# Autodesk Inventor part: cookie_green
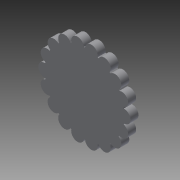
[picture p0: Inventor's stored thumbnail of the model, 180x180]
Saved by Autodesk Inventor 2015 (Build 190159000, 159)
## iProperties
Created: 2017-04
Part Number: cookie_green
Material: Generic
Document SubType Name: Modeling
Designer: mcalderon
Density: 1 g/cm^3
Appearance: Default
Author: mcalderon
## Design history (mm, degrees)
sketch "Sketch1"
  geometry: L1 (25, 0)-(-25, 0); L2 (0, 25)-(0, -25); A1 r 4 centre (25, 0) between (24.68, -3.987) and (24.68, 3.987); A2 r 4 centre (23.492, 8.551) between (24.555, 4.694) and (21.828, 12.188); A3 r 4 centre (19.151, 16.07) between (21.469, 12.81) and (16.343, 18.918); A4 r 4 centre (12.5, 21.651) between (15.793, 19.38) and (8.887, 23.367); A5 r 4 centre (4.341, 24.62) between (8.212, 23.613) and (0.359, 24.997); A6 r 4 centre (-4.341, 24.62) between (-0.359, 24.997) and (-8.212, 23.613); A7 r 4 centre (-12.5, 21.651) between (-8.887, 23.367) and (-15.793, 19.38); A8 r 4 centre (-19.151, 16.07) between (-16.343, 18.918) and (-21.469, 12.81); A9 r 4 centre (-23.492, 8.551) between (-21.828, 12.188) and (-24.555, 4.694); A10 r 4 centre (-25, 0) between (-24.68, 3.987) and (-24.68, -3.987); A11 r 4 centre (-23.492, -8.551) between (-24.555, -4.694) and (-21.828, -12.188); A12 r 4 centre (-19.151, -16.07) between (-21.469, -12.81) and (-16.343, -18.918); A13 r 4 centre (-12.5, -21.651) between (-15.793, -19.38) and (-8.887, -23.367); A14 r 4 centre (-4.341, -24.62) between (-8.212, -23.613) and (-0.359, -24.997); A15 r 4 centre (4.341, -24.62) between (0.359, -24.997) and (8.212, -23.613); A16 r 4 centre (12.5, -21.651) between (8.887, -23.367) and (15.793, -19.38); A17 r 4 centre (19.151, -16.07) between (16.343, -18.918) and (21.469, -12.81); A18 r 4 centre (23.492, -8.551) between (21.828, -12.188) and (24.555, -4.694); A19 r 25 centre (0, 0) between (21.469, -12.81) and (21.828, -12.188); A20 r 25 centre (0, 0) between (15.793, -19.38) and (16.343, -18.918); A21 r 25 centre (0, 0) between (8.212, -23.613) and (8.887, -23.367); A22 r 25 centre (0, 0) between (-0.359, -24.997) and (0.359, -24.997); A23 r 25 centre (0, 0) between (-8.887, -23.367) and (-8.212, -23.613); A24 r 25 centre (0, 0) between (-16.343, -18.918) and (-15.793, -19.38); A25 r 25 centre (0, 0) between (-21.828, -12.188) and (-21.469, -12.81); A26 r 25 centre (0, 0) between (-24.68, -3.987) and (-24.555, -4.694); A27 r 25 centre (0, 0) between (-24.555, 4.694) and (-24.68, 3.987); A28 r 25 centre (0, 0) between (-21.469, 12.81) and (-21.828, 12.188); A29 r 25 centre (0, 0) between (-15.793, 19.38) and (-16.343, 18.918); A30 r 25 centre (0, 0) between (-8.212, 23.613) and (-8.887, 23.367); A31 r 25 centre (0, 0) between (0.359, 24.997) and (-0.359, 24.997); A32 r 25 centre (0, 0) between (8.887, 23.367) and (8.212, 23.613); A33 r 25 centre (0, 0) between (16.343, 18.918) and (15.793, 19.38); A34 r 25 centre (0, 0) between (21.828, 12.188) and (21.469, 12.81); A35 r 25 centre (0, 0) between (24.555, -4.694) and (24.68, -3.987); A36 r 25 centre (0, 0) between (24.68, 3.987) and (24.555, 4.694); 1 further point
  constraints: 74 point on circle, 36 centre point, 4 end point, 1 coincident, 1 perpendicular, 73 other
  dimensions: "d1" = 8 diameter of A1; "d4" = 360 deg dimension on point (0, 0) L1.start (derived)
extrude "Extrusion1" new body sketch "Sketch1" distance "d6" = 5; taper "d7" = 0 deg
sketch "Sketch2" dims "d28" = 3, "d34" = 10
  geometry: L1 (5.643, -19.187)-(5.643, 19.187); L2 (-31.254, 0)-(33.406, 0); L3 (-8.015, 2.569)-(-8.798, 14.543); L4 (-6.756, 3.387)-(-8.121, 4.191); L5 (-6.756, -3.387)-(-8.121, -4.191); L6 (-8.015, -2.569)-(-8.798, -14.543); A1 r 20 centre (0, 0) between (5.643, -19.187) and (5.643, 19.187); A2 r 6 centre (-3.731, 8.569) between (-6.756, 3.387) and (-8.633, 12.028); A3 r 6 centre (-3.731, -8.569) between (-8.633, -12.028) and (-6.756, -3.387); 15 further points
  constraints: 13 symmetric about line, 12 end point, 6 point on circle, 6 point on line, 5 horizontal, 3 centre point, 1 coincident, 1 vertical, 35 other
  dimensions: "d25" = 12 diameter of A2; "d27" = 12 distance of L3.start L3.end; "d31" = 3 distance of point (-8.111, 4.032) point (-8.306, 7.025)
extrude "Extrusion7" join sketch "Sketch2" distance "d36" = 2; taper "d37" = 0 deg
body "Solid1"
